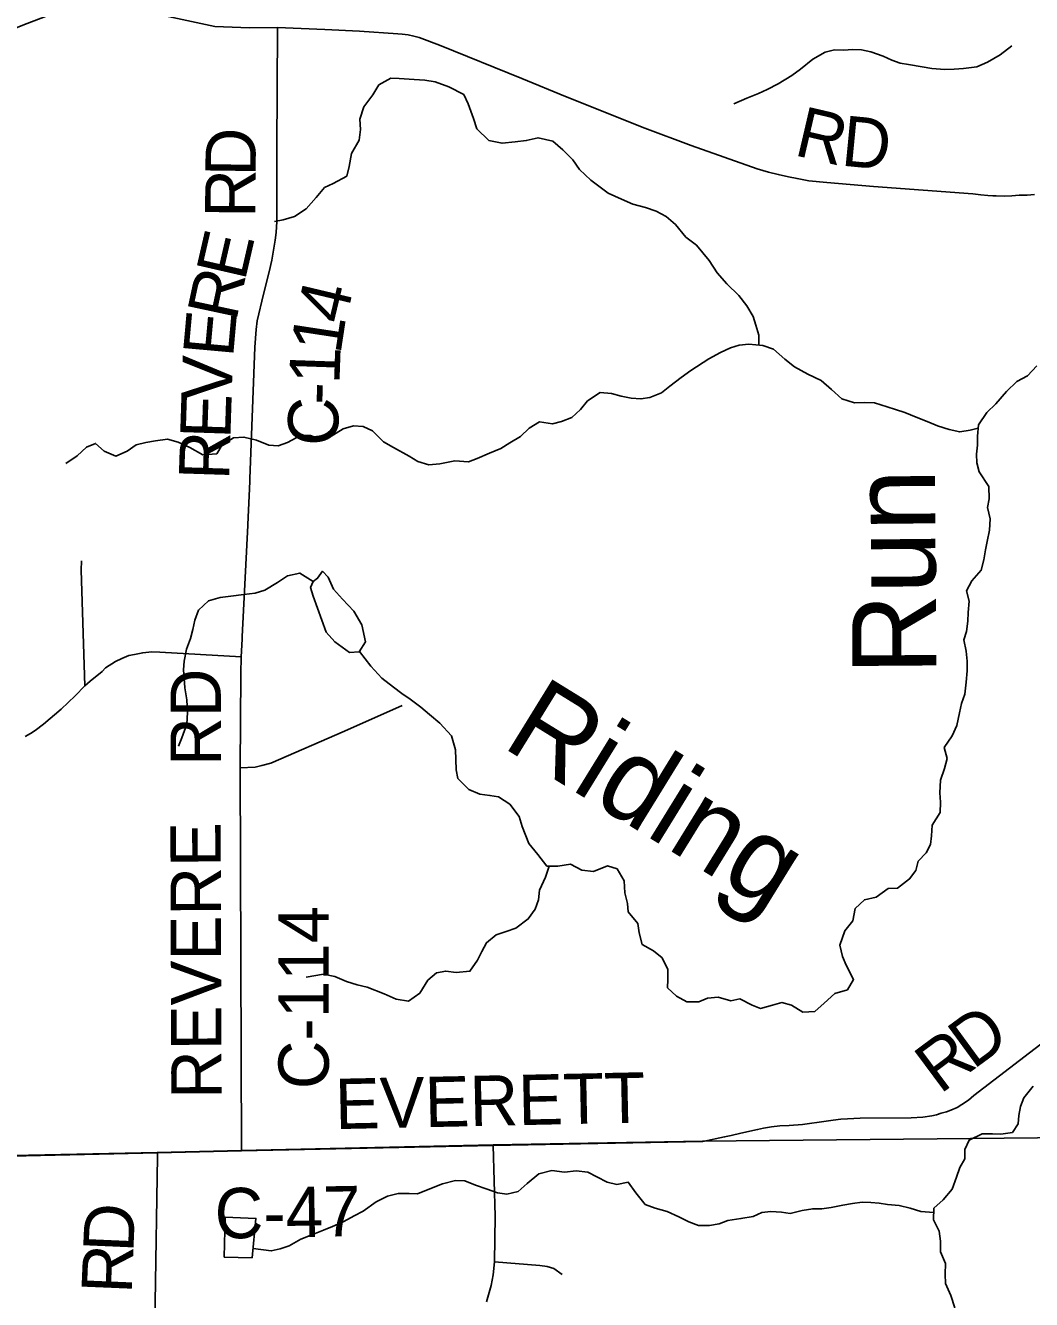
# Model space of a CAD drawing. Extents: x 0 to 34, y 0 to 22.
# Drawn here: x 6.774 to 7.911, y 15.737 to 17.175 of the extents above; entities that cross this region are included whole.
import ezdxf

# ---------------------------------------------------------------- set-up
doc = ezdxf.new("R2010")
doc.units = 0
for name, color, linetype in [('Default', 7, 'Continuous'), ('GM_X_City_Street', 7, 'Continuous'), ('GM_X_County_Road', 7, 'Continuous'), ('GM_X_County_Road_Text', 7, 'Continuous'), ('GM_X_Minor_Lake', 7, 'Continuous'), ('GM_X_Minor_River', 7, 'Continuous'), ('GM_X_Minor_River_Text', 7, 'Continuous'), ('GM_X_Township_Road', 7, 'Continuous')]:
    doc.layers.add(name, color=color, linetype=linetype)

msp = doc.modelspace()

# ---------------------------------------------------------------- linework, layer by layer
at = {"layer": 'Default'}
for points in [[(6.5781, 15.8955), (6.9232, 15.9027), (7.0184, 15.9049), (7.3026, 15.9113), (7.5392, 15.9156), (8.2582, 15.9227), (8.2536, 16.1438), (8.2434, 16.7876), (8.2417, 17.2403), (8.2392, 17.3521), (8.2361, 17.5877), (8.2338, 18.0126), (8.2283, 18.4271), (8.2254, 18.6464), (8.2237, 18.7271), (8.2232, 18.7798), (8.2229, 18.8136), (8.2216, 18.8361), (8.2195, 18.875), (8.2069, 19.4369), (8.2061, 19.4737), (8.1995, 19.7718), (8.1859, 20.3892)], [(8.4608, 15.4787), (8.4608, 15.9241), (8.2582, 15.9227), (7.5392, 15.9156), (7.3026, 15.9113), (7.0184, 15.9049), (6.9232, 15.9027), (6.5781, 15.8955), (6.4918, 15.8937), (6.4353, 15.8916), (6.4145, 15.8911), (6.2639, 15.8885), (6.1922, 15.8873), (6.1703, 15.8865), (6.065, 15.8836), (5.9591, 15.8823), (5.7768, 15.8771), (5.0185, 15.8642), (4.6273, 15.8569), (4.3446, 15.8524)]]:
    msp.add_lwpolyline(points, dxfattribs=at)
at = {"layer": 'GM_X_City_Street'}
for points in [[(6.8416, 16.4295), (6.8372, 16.5599), (6.8379, 16.5704)], [(6.7743, 16.3723), (6.7803, 16.3756), (6.7855, 16.379), (6.7949, 16.3862), (6.8148, 16.4032), (6.8306, 16.418), (6.8416, 16.4295), (6.8475, 16.4348), (6.8611, 16.4455), (6.865, 16.4497), (6.876, 16.4569), (6.8834, 16.4604), (6.8913, 16.4635), (6.8977, 16.4649), (6.9069, 16.4668), (6.9173, 16.4677), (6.9262, 16.4674), (7.0179, 16.4621)]]:
    msp.add_lwpolyline(points, dxfattribs=at)
at = {"layer": 'GM_X_County_Road'}
for p, q in [((7.017, 16.3368), (7.0175, 16.4425)), ((7.0186, 15.9044), (7.017, 16.3368)), ((6.6359, 15.8961), (6.9234, 15.9021)), ((6.9234, 15.9021), (7.0186, 15.9044))]:
    msp.add_line(p, q, dxfattribs=at)
for points in [[(6.3969, 17.1561), (6.4792, 17.1605), (6.4835, 17.1608), (6.5551, 17.1657), (6.5991, 17.1683), (6.611, 17.1686), (6.6385, 17.1673), (6.6798, 17.1614), (6.7109, 17.1587), (6.7298, 17.1607), (6.7479, 17.1657), (6.7764, 17.1772), (6.8049, 17.1881), (6.8209, 17.1938), (6.8314, 17.197), (6.8397, 17.1986), (6.8472, 17.1994), (6.8548, 17.2001), (6.8677, 17.1991), (6.9249, 17.1872), (6.9884, 17.1736), (7.0275, 17.1723), (7.0591, 17.1724)], [(7.0279, 16.66), (7.028, 16.663), (7.0334, 16.8116), (7.0349, 16.8315), (7.0361, 16.8413), (7.0434, 16.8717), (7.0496, 16.8967), (7.0526, 16.9098), (7.0566, 16.9323), (7.0577, 16.9412), (7.0582, 16.9537), (7.0582, 17.0349), (7.0591, 17.1724)], [(7.0591, 17.1724), (7.1125, 17.1702), (7.1515, 17.1683), (7.1951, 17.1654), (7.2, 17.1649), (7.2065, 17.1641), (7.2131, 17.1626), (7.219, 17.1611), (7.242, 17.1526), (7.3349, 17.1148), (7.3844, 17.0948), (7.474, 17.0588), (7.5261, 17.0392), (7.6006, 17.0129), (7.6137, 17.0092), (7.6245, 17.0067), (7.6363, 17.0038), (7.6459, 17.0019), (7.6591, 16.9996), (7.6793, 16.9974), (7.7323, 16.9932), (7.8445, 16.9846), (7.8535, 16.9836), (7.8614, 16.9829), (7.8669, 16.9826)], [(7.8669, 16.9826), (7.8707, 16.9824), (7.8796, 16.9822), (7.8884, 16.9824), (7.8965, 16.9832), (7.9058, 16.9834), (7.914, 16.9841)], [(7.0256, 16.6105), (7.0257, 16.6115), (7.0279, 16.66)], [(7.019, 16.482), (7.0191, 16.485), (7.0256, 16.6105)], [(7.0175, 16.4425), (7.0175, 16.4435), (7.0179, 16.4621), (7.019, 16.482)], [(7.5715, 15.9218), (7.5823, 15.9243), (7.6012, 15.9286), (7.6081, 15.9302), (7.6171, 15.9315), (7.6265, 15.9327), (7.637, 15.933), (7.6518, 15.9342), (7.6785, 15.9379), (7.6867, 15.9391), (7.6952, 15.9401), (7.7029, 15.9408), (7.7169, 15.9416), (7.7748, 15.9418), (7.788, 15.9426), (7.7979, 15.944), (7.8032, 15.9453), (7.8086, 15.9469), (7.8146, 15.9487), (7.8195, 15.9506), (7.8265, 15.9536), (7.8319, 15.9567), (7.8393, 15.9619), (7.8455, 15.9669), (7.9373, 16.0373)], [(7.0186, 15.9044), (7.3028, 15.9107), (7.5394, 15.9151), (7.564, 15.9202), (7.5715, 15.9218)], [(6.9171, 14.976), (6.917, 14.9819), (6.9178, 15.0863), (6.9178, 15.1894), (6.9176, 15.438), (6.9192, 15.5433), (6.9197, 15.5792), (6.92, 15.648), (6.9211, 15.7334), (6.9234, 15.8982), (6.9234, 15.9021)]]:
    msp.add_lwpolyline(points, dxfattribs=at)
at = {"layer": 'GM_X_Minor_Lake'}
for points in [[(7.1139, 16.4901), (7.1239, 16.4792), (7.1403, 16.4672), (7.1513, 16.4677), (7.1584, 16.4791), (7.1544, 16.4981), (7.1452, 16.5136), (7.1326, 16.5271), (7.1222, 16.5384), (7.1164, 16.552), (7.1099, 16.5588), (7.1043, 16.5508), (7.0994, 16.5473), (7.0964, 16.5404), (7.0995, 16.5306)], [(7.0995, 16.5306), (7.1139, 16.4901)], [(7.0305, 15.7837), (7.0347, 15.8282), (6.9998, 15.8298), (6.9987, 15.7846)], [(6.9987, 15.7846), (7.0305, 15.7837)]]:
    msp.add_lwpolyline(points, dxfattribs=at)
at = {"layer": 'GM_X_Minor_River'}
for points in [[(7.5743, 17.0865), (7.589, 17.0928), (7.6022, 17.0982), (7.6121, 17.1025), (7.6245, 17.109), (7.64, 17.1183), (7.6498, 17.1256), (7.6637, 17.1368), (7.6777, 17.1445), (7.6882, 17.1473), (7.6985, 17.147), (7.7083, 17.1478), (7.7186, 17.1472), (7.7292, 17.145), (7.7429, 17.1402), (7.7528, 17.1357), (7.7623, 17.1324), (7.7718, 17.1306), (7.787, 17.1281), (7.798, 17.1263), (7.8128, 17.1253), (7.8234, 17.1254), (7.8336, 17.1262), (7.8487, 17.1283), (7.8608, 17.1333), (7.8752, 17.1418), (7.8883, 17.1518)], [(7.6027, 16.8139), (7.6027, 16.8251), (7.5992, 16.8365), (7.5961, 16.8463), (7.5891, 16.8584), (7.5799, 16.8701), (7.5666, 16.8833), (7.5555, 16.8957), (7.5466, 16.9097), (7.5321, 16.927), (7.5202, 16.936), (7.5084, 16.95), (7.4981, 16.959), (7.4866, 16.9653), (7.4745, 16.9694), (7.4604, 16.973), (7.4475, 16.9786), (7.4326, 16.9857), (7.4128, 17.0003), (7.4002, 17.0124), (7.3925, 17.0233), (7.3814, 17.0346), (7.37, 17.0443), (7.3533, 17.048), (7.34, 17.0448), (7.3275, 17.0436), (7.3127, 17.0419), (7.2979, 17.0448), (7.2842, 17.0583), (7.2803, 17.0697), (7.2745, 17.0864), (7.2694, 17.0969), (7.2527, 17.1055), (7.2371, 17.1111), (7.2253, 17.1129), (7.2136, 17.1139), (7.1965, 17.1149), (7.187, 17.1155), (7.1734, 17.1078), (7.1667, 17.0967), (7.1566, 17.083), (7.1522, 17.0689), (7.1527, 17.0575), (7.1512, 17.0453), (7.1427, 17.0304), (7.1401, 17.0156), (7.1372, 17.0049), (7.1221, 16.9964), (7.1123, 16.9918), (7.1029, 16.9807), (7.0916, 16.9677), (7.0784, 16.9592), (7.0656, 16.9556), (7.0557, 16.9536)], [(7.8504, 16.7204), (7.8413, 16.718), (7.8295, 16.716), (7.8174, 16.7186), (7.8045, 16.723), (7.7946, 16.7271), (7.7805, 16.7326), (7.7676, 16.7378), (7.7569, 16.7415), (7.7474, 16.7445), (7.7334, 16.7489), (7.722, 16.7492), (7.7106, 16.7487), (7.6962, 16.7535), (7.6847, 16.764), (7.6732, 16.7742), (7.658, 16.7812), (7.6428, 16.7894), (7.6321, 16.7981), (7.6191, 16.8093), (7.6073, 16.8134), (7.5914, 16.8152), (7.5804, 16.8139), (7.5706, 16.8108), (7.5593, 16.8057), (7.5461, 16.7984), (7.5257, 16.7853), (7.5151, 16.7776), (7.5023, 16.7676), (7.4926, 16.7603), (7.4797, 16.7549), (7.4695, 16.7532), (7.4585, 16.7543), (7.4471, 16.7564), (7.4361, 16.7594), (7.4236, 16.7604), (7.4092, 16.7512), (7.4014, 16.7412), (7.3916, 16.7324), (7.3799, 16.7277), (7.3697, 16.725), (7.3549, 16.7275), (7.3432, 16.7201), (7.3334, 16.7109), (7.3213, 16.7036), (7.3111, 16.6974), (7.2983, 16.692), (7.2847, 16.6862), (7.2749, 16.6823), (7.2593, 16.6833), (7.2423, 16.6801), (7.2298, 16.6788), (7.2176, 16.6825), (7.2077, 16.6885), (7.1902, 16.6986), (7.1788, 16.7049), (7.1662, 16.7173), (7.1559, 16.7222), (7.1449, 16.7228), (7.1332, 16.7197), (7.1173, 16.7096), (7.106, 16.7084), (7.0965, 16.7121), (7.0851, 16.712), (7.0704, 16.7039), (7.0598, 16.7004), (7.0492, 16.701), (7.0355, 16.7066), (7.0211, 16.7102), (7.0093, 16.7094), (6.9965, 16.7013), (6.9905, 16.6914), (6.9746, 16.6901), (6.9601, 16.6983), (6.9468, 16.7046), (6.9347, 16.7079), (6.9214, 16.7059), (6.9104, 16.7039), (6.8995, 16.7015), (6.8893, 16.6942), (6.8765, 16.6888), (6.8635, 16.6943), (6.8536, 16.703), (6.8434, 16.6987), (6.8329, 16.6891), (6.82, 16.6802)], [(7.9165, 16.7905), (7.9059, 16.7794), (7.8939, 16.7728), (7.8822, 16.7617), (7.8702, 16.7479), (7.86, 16.738), (7.8507, 16.7242), (7.8497, 16.7113), (7.8494, 16.701), (7.8483, 16.6911), (7.8488, 16.6813), (7.8515, 16.671), (7.8623, 16.6544), (7.8628, 16.6404), (7.861, 16.6309), (7.8637, 16.618), (7.8631, 16.6051), (7.8605, 16.5925), (7.8587, 16.583), (7.8569, 16.5716), (7.8536, 16.5598), (7.8431, 16.5479), (7.8371, 16.5368), (7.8403, 16.5251), (7.8392, 16.5122), (7.8386, 16.5023), (7.8371, 16.4909), (7.8342, 16.4814), (7.8366, 16.4685), (7.8378, 16.4571), (7.8379, 16.4465), (7.8369, 16.4335), (7.8351, 16.4202), (7.8314, 16.4096), (7.8292, 16.3989), (7.8263, 16.3845), (7.8211, 16.373), (7.8121, 16.36), (7.8153, 16.3475), (7.8123, 16.3361), (7.8079, 16.3231), (7.8069, 16.3087), (7.8077, 16.2981), (7.8074, 16.2863), (7.7985, 16.2722), (7.7978, 16.26), (7.7964, 16.2505), (7.7915, 16.241), (7.7825, 16.2314), (7.7799, 16.2211), (7.7728, 16.2115), (7.7593, 16.2012), (7.7487, 16.2007), (7.7351, 16.191), (7.7219, 16.1879), (7.7113, 16.1779), (7.7088, 16.1642), (7.6998, 16.1527), (7.6942, 16.1367), (7.697, 16.1238), (7.7013, 16.114), (7.7097, 16.0981), (7.7026, 16.0863), (7.6883, 16.082)], [(7.0994, 16.5473), (7.0842, 16.5567), (7.0705, 16.5535), (7.0589, 16.5462), (7.0449, 16.5373), (7.0339, 16.5342), (7.0211, 16.5325), (7.0063, 16.5305), (6.9942, 16.5292), (6.981, 16.5253), (6.9697, 16.5149), (6.9656, 16.5035), (6.9634, 16.4929), (6.9608, 16.483), (6.9564, 16.4708), (6.9535, 16.4571), (6.9528, 16.4476), (6.9537, 16.4381), (6.9545, 16.4271), (6.9565, 16.4138), (6.9574, 16.3994), (6.9567, 16.3861), (6.9512, 16.3708), (6.9471, 16.3613)], [(7.6883, 16.082), (7.6766, 16.0713), (7.6657, 16.0617), (7.6524, 16.0611), (7.6395, 16.069), (7.6285, 16.0719), (7.6179, 16.0688), (7.6046, 16.0653), (7.5951, 16.069), (7.5811, 16.076), (7.5712, 16.074), (7.5568, 16.0781), (7.5447, 16.0768), (7.5348, 16.0726), (7.5212, 16.0728), (7.5098, 16.0792), (7.4995, 16.0886), (7.4997, 16.0981), (7.4997, 16.1094), (7.4935, 16.1223), (7.4836, 16.1302), (7.471, 16.1373), (7.4675, 16.1505), (7.4659, 16.1612), (7.4551, 16.1743), (7.4543, 16.1838), (7.4515, 16.1956), (7.4507, 16.2092), (7.4426, 16.2228), (7.4316, 16.2261), (7.4161, 16.2199), (7.4028, 16.2213), (7.3898, 16.228), (7.3755, 16.226), (7.3633, 16.2259), (7.353, 16.2391), (7.343, 16.2515), (7.3353, 16.2708), (7.3321, 16.2818), (7.3214, 16.2957), (7.3085, 16.304), (7.299, 16.3058), (7.2876, 16.3072), (7.275, 16.3124), (7.2628, 16.3248), (7.2608, 16.3347), (7.2603, 16.3464), (7.2602, 16.3571), (7.2556, 16.373), (7.2425, 16.3873), (7.2307, 16.397), (7.2208, 16.4053), (7.209, 16.4143), (7.1994, 16.4207), (7.1899, 16.4278), (7.1769, 16.4379), (7.1643, 16.4515), (7.1515, 16.4681)], [(7.366, 16.2259), (7.3619, 16.2133), (7.3548, 16.1988), (7.3538, 16.1878), (7.3501, 16.1775), (7.3422, 16.1664), (7.3283, 16.1557), (7.3173, 16.1521), (7.306, 16.1482), (7.2951, 16.1394), (7.2899, 16.1295), (7.285, 16.1196), (7.2764, 16.1073), (7.2609, 16.1057), (7.2491, 16.1074), (7.2385, 16.1054), (7.2287, 16.097), (7.2198, 16.0825), (7.207, 16.0736), (7.1929, 16.0758), (7.1796, 16.0817), (7.1602, 16.0891), (7.1492, 16.0921), (7.137, 16.0957), (7.1237, 16.1013), (7.1112, 16.1039), (7.0915, 16.1006)], [(7.9124, 15.9774), (7.9019, 15.9644), (7.8982, 15.9545), (7.8964, 15.9446), (7.8954, 15.9351), (7.889, 15.9252), (7.8761, 15.9235), (7.8667, 15.9238), (7.8549, 15.9237), (7.8402, 15.9167), (7.8353, 15.9061), (7.8354, 15.8954), (7.8295, 15.8859), (7.8258, 15.8748), (7.8209, 15.8611), (7.8108, 15.8492), (7.8003, 15.84), (7.8, 15.8267), (7.8062, 15.8139), (7.8078, 15.8025), (7.8079, 15.7907), (7.8133, 15.7775), (7.8131, 15.7653), (7.8135, 15.7547), (7.8193, 15.7411), (7.824, 15.7275)], [(7.8002, 15.8348), (7.7855, 15.8361), (7.7737, 15.8398), (7.7612, 15.8427), (7.7479, 15.8441), (7.7384, 15.8455), (7.729, 15.8462), (7.7195, 15.8465), (7.7085, 15.8452), (7.6975, 15.8432), (7.6843, 15.8404), (7.6737, 15.8392), (7.6635, 15.8391), (7.6517, 15.8371), (7.6381, 15.8339), (7.6282, 15.8354), (7.6161, 15.836), (7.6059, 15.8348), (7.5961, 15.8305), (7.5824, 15.8281), (7.5677, 15.826), (7.5578, 15.8222), (7.5469, 15.8201), (7.5344, 15.8204), (7.5237, 15.8245), (7.5123, 15.8301), (7.499, 15.836), (7.4857, 15.8397), (7.4743, 15.8438), (7.4639, 15.8573), (7.4551, 15.869), (7.4422, 15.8666), (7.4312, 15.8692), (7.4198, 15.8751), (7.4095, 15.8804), (7.3962, 15.8818), (7.383, 15.8805), (7.3689, 15.8823), (7.3542, 15.8787), (7.341, 15.8676), (7.3309, 15.8587), (7.318, 15.8556), (7.3077, 15.857), (7.296, 15.8611), (7.2827, 15.8659), (7.2705, 15.8707), (7.2602, 15.871), (7.2455, 15.8674), (7.233, 15.8624), (7.2172, 15.8561), (7.2077, 15.8564), (7.1952, 15.8563), (7.1834, 15.8535), (7.1706, 15.847), (7.1559, 15.8366), (7.1457, 15.8311), (7.134, 15.8246), (7.1212, 15.8191), (7.111, 15.8149), (7.0978, 15.8098), (7.0853, 15.8048), (7.0721, 15.7974), (7.0619, 15.7939), (7.0521, 15.7915), (7.0315, 15.7942)]]:
    msp.add_lwpolyline(points, dxfattribs=at)
at = {"layer": 'GM_X_Township_Road'}
for points in [[(7.017, 16.3368), (7.034, 16.3377), (7.0412, 16.3394), (7.0515, 16.3423), (7.1347, 16.3784), (7.1999, 16.4071)], [(7.295, 15.7342), (7.3003, 15.7526), (7.3026, 15.7646), (7.304, 15.7791), (7.3049, 15.8308), (7.3028, 15.9107)], [(7.304, 15.7791), (7.3554, 15.7752), (7.3637, 15.774), (7.3711, 15.7717), (7.3807, 15.7648)]]:
    msp.add_lwpolyline(points, dxfattribs=at)

# ---------------------------------------------------------------- texts
at = {"layer": 'GM_X_County_Road_Text'}
for s, height, rotation, p in [('R', 0.0568, 346.8612, (7.6411, 17.0287)), ('D', 0.0568, 354.479, (7.6945, 17.0168)), ('D', 0.0568, 89.235, (7.0343, 17.0042)), ('R', 0.0568, 89.7933, (7.0341, 16.9577)), ('E', 0.0568, 77.0063, (7.0221, 16.8853)), ('R', 0.0568, 77.9292, (7.0123, 16.8399)), ('4', 0.0568, 76.6617, (7.1351, 16.8361)), ('E', 0.0568, 84.8545, (7.0088, 16.7994)), ('1', 0.0568, 81.3444, (7.1301, 16.8027)), ('V', 0.0568, 88.0397, (7.0071, 16.7503)), ('1', 0.0568, 88.043, (7.129, 16.7695)), ('-', 0.0568, 88.2669, (7.1283, 16.7462)), ('E', 0.0568, 88.1531, (7.0058, 16.7078)), ('C', 0.0568, 88.3137, (7.127, 16.6996)), ('R', 0.0568, 88.1496, (7.0043, 16.6612)), ('RD', 0.05682, 90, (6.9951, 16.3391)), ('REVERE', 0.05682, 90.1767, (6.9959, 15.9632)), ('C-114', 0.05682, 90, (7.117, 15.9741)), ('D', 0.0568, 36.2521, (7.8446, 15.9956)), ('R', 0.0568, 36.6357, (7.8073, 15.9678)), ('EVERETT', 0.05682, 1.2356, (7.1246, 15.929)), ('C-47', 0.05682, 1.0238, (6.9886, 15.8054)), ('D', 0.0568, 87.5076, (6.8962, 15.7893)), ('R', 0.0568, 87.5989, (6.8943, 15.7427))]:
    msp.add_text(s, height=height, rotation=rotation, dxfattribs=at).set_placement(p)
at = {"layer": 'GM_X_Minor_River_Text'}
for s, height, rotation, p in [('Run', 0.09475, 90.4387, (7.8032, 16.4421)), ('Riding', 0.09474, 328.35, (7.3109, 16.3614))]:
    msp.add_text(s, height=height, rotation=rotation, dxfattribs=at).set_placement(p)

doc.saveas('drawing.dxf')
